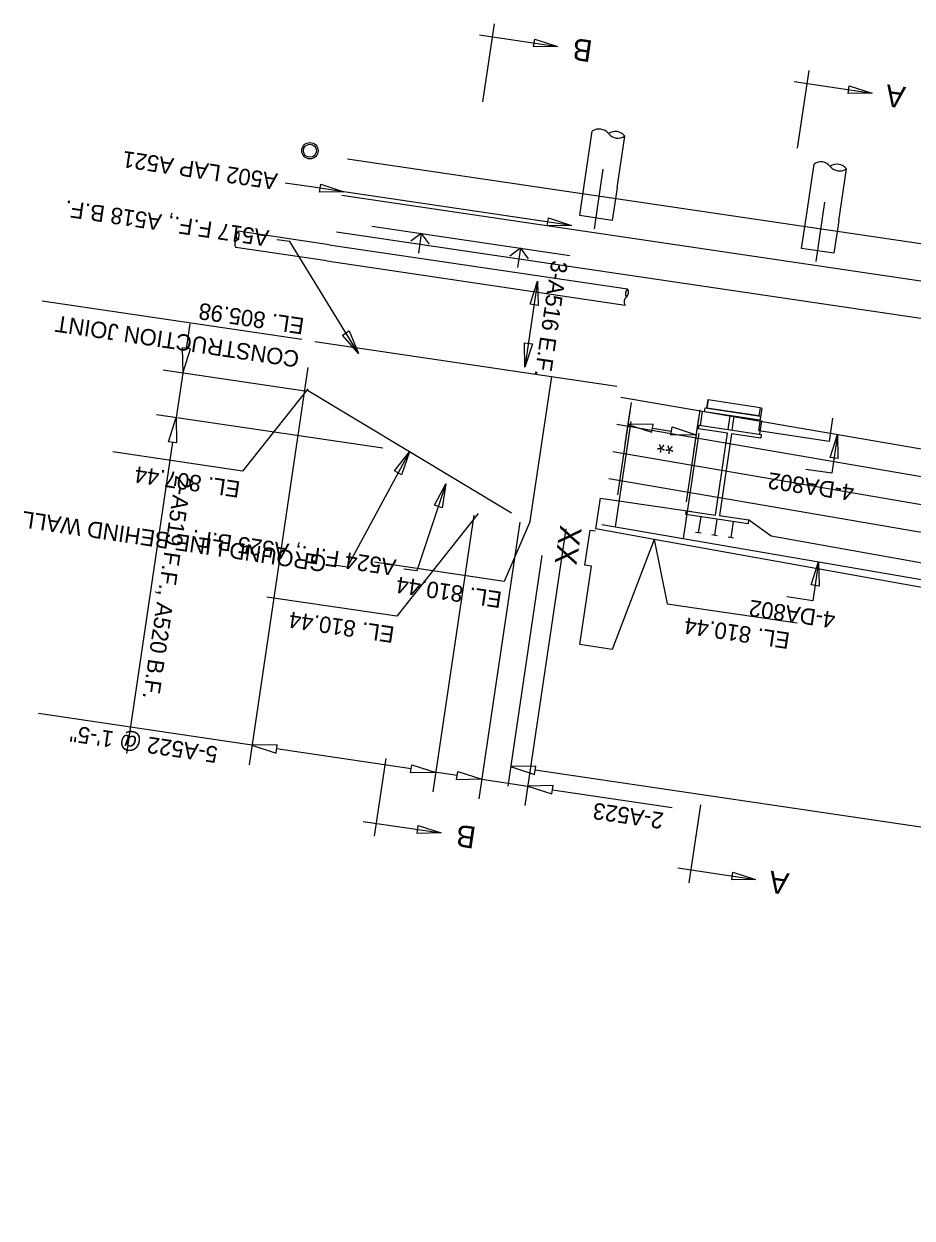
# Model space of a CAD drawing. Extents: x 1468952 to 1469933, y 573916 to 574220.
# Drawn here: x 1468962.44 to 1468989.52, y 574056.5 to 574092.91 of the extents above; entities that cross this region are included whole.
import ezdxf

# ---------------------------------------------------------------- set-up
doc = ezdxf.new("R2010")
doc.units = 0
for name, color, linetype in [('BR_P_Beam_Object', 7, 'Continuous'), ('BR_P_Beam_Stl_Det', 7, 'Continuous'), ('BR_P_Gen_Centerline', 7, 'Continuous'), ('BR_P_Gen_Phase_Construction', 7, 'Continuous'), ('BR_P_Sub_Centerline', 7, 'Continuous'), ('BR_P_Sub_Deep_Centerline', 7, 'Continuous'), ('BR_P_Sub_Foot_Centerline', 7, 'Continuous'), ('BR_P_Sub_Foot_Hidden', 7, 'Continuous'), ('BR_P_Sub_Text', 7, 'Continuous'), ('BR_X_SV_Beam_Seat', 7, 'Continuous'), ('Default', 7, 'Continuous'), ('GE_P_CL_50', 7, 'Continuous'), ('GK_Cells', 7, 'Continuous'), ('PF_X_Ground_Line', 7, 'Continuous'), ('PV_X_EOP', 7, 'Continuous'), ('SV_X_Text_Elevation', 7, 'Continuous'), ('UT_X_Water', 7, 'Continuous')]:
    doc.layers.add(name, color=color, linetype=linetype)

# ---------------------------------------------------------------- blocks, each defined once
blk = doc.blocks.new('arrowOhio')
at = {"layer": 'Default'}
blk.add_lwpolyline([(0.00381, 0.000635), (0.00381, -0.000635), (0, 0)], close=True, dxfattribs=at)

msp = doc.modelspace()

# ---------------------------------------------------------------- linework, layer by layer
at = {"layer": 'BR_P_Beam_Object'}
for p, q in [((1468971.743, 574086.174), (1468980.843, 574084.827)), ((1468971.669, 574085.68), (1468980.77, 574084.333)), ((1468977.303, 574077.995), (1468971.084, 574081.728))]:
    msp.add_line(p, q, dxfattribs=at)
for centre, start, end in [((1468980.955, 574084.684), 127.976, 215.1816), ((1468980.695, 574084.723), 307.976, 35.1816), ((1468980.918, 574084.437), 127.976, 215.1816)]:
    msp.add_arc(centre, 0.181, start, end, dxfattribs=at)
at = {"layer": 'BR_P_Beam_Stl_Det'}
for p, q in [((1468976.432, 574090.535), (1468976.783, 574092.909)), ((1468976.329, 574092.572), (1468978.703, 574092.22)), ((1468986.025, 574089.115), (1468986.377, 574091.489)), ((1468985.922, 574091.152), (1468988.296, 574090.8)), ((1469004.297, 574084.051), (1468972.298, 574088.788)), ((1469010.688, 574081.967), (1468972.133, 574087.675)), ((1469010.523, 574080.854), (1468971.968, 574086.562)), ((1468973.468, 574070.513), (1468973.116, 574068.139)), ((1468983.061, 574069.093), (1468982.709, 574066.719)), ((1468972.779, 574068.593), (1468975.153, 574068.242)), ((1468982.372, 574067.173), (1468984.746, 574066.821))]:
    msp.add_line(p, q, dxfattribs=at)
at = {"layer": 'BR_P_Gen_Centerline'}
for p, q in [((1468971.743, 574086.174), (1468968.973, 574086.585)), ((1468971.669, 574085.68), (1468968.9, 574086.09))]:
    msp.add_line(p, q, dxfattribs=at)
for radius in [0.25, 0.2]:
    msp.add_circle((1468971.156, 574089.041), radius, dxfattribs=at)
for centre, start, end in [((1468969.084, 574086.442), 127.976, 215.1816), ((1468968.825, 574086.48), 307.976, 35.1816), ((1468969.048, 574086.194), 127.976, 215.1816)]:
    msp.add_arc(centre, 0.181, start, end, dxfattribs=at)
at = {"layer": 'BR_P_Gen_Phase_Construction'}
for p, q in [((1468979.531, 574088.054), (1468979.766, 574089.637)), ((1468980.52, 574087.908), (1468980.755, 574089.49)), ((1468986.291, 574087.053), (1468986.525, 574088.636)), ((1468987.28, 574086.907), (1468987.514, 574088.49))]:
    msp.add_line(p, q, dxfattribs=at)
for centre, start, end in [((1468979.974, 574089.341), 37.976, 125.1816), ((1468980.469, 574089.267), 37.976, 125.1816), ((1468980.546, 574089.787), 217.976, 305.1816), ((1468986.734, 574088.34), 37.976, 125.1816), ((1468987.229, 574088.267), 37.976, 125.1816), ((1468987.306, 574088.786), 217.976, 305.1816)]:
    msp.add_arc(centre, 0.362, start, end, dxfattribs=at)
at = {"layer": 'BR_P_Sub_Centerline'}
for p, q in [((1468979.385, 574087.065), (1468979.531, 574088.054)), ((1468980.52, 574087.908), (1468980.374, 574086.918)), ((1468980.374, 574086.918), (1468979.385, 574087.065)), ((1468986.144, 574086.064), (1468986.291, 574087.053)), ((1468987.28, 574086.907), (1468987.134, 574085.918)), ((1468987.134, 574085.918), (1468986.144, 574086.064))]:
    msp.add_line(p, q, dxfattribs=at)
at = {"layer": 'BR_P_Sub_Deep_Centerline'}
msp.add_line((1468977.874, 574077.746), (1468978.527, 574082.158), dxfattribs=at)
at = {"layer": 'BR_P_Sub_Foot_Centerline'}
for p, q in [((1468983.062, 574080.665), (1468983.124, 574081.087)), ((1468983.909, 574080.539), (1468983.972, 574080.962)), ((1468984.028, 574080.522), (1468984.091, 574080.944)), ((1468984.876, 574080.396), (1468984.938, 574080.819))]:
    msp.add_line(p, q, dxfattribs=at)
at = {"layer": 'BR_P_Sub_Foot_Hidden'}
msp.add_line((1468981.648, 574077.187), (1468979.871, 574077.508), dxfattribs=at)
at = {"layer": 'BR_P_Sub_Text'}
for p, q in [((1468980.635, 574081.53), (1468997.15, 574078.687)), ((1468980.947, 574081.36), (1468980.531, 574078.553)), ((1468983.043, 574081.14), (1468982.627, 574078.332)), ((1468980.47, 574077.573), (1468980.946, 574080.788)), ((1468980.512, 574080.703), (1468997.027, 574077.86)), ((1468982.546, 574077.216), (1468983.022, 574080.431)), ((1468980.39, 574079.875), (1468996.905, 574077.032)), ((1468980.267, 574079.048), (1468996.782, 574076.205)), ((1468980.059, 574077.644), (1468996.575, 574074.801))]:
    msp.add_line(p, q, dxfattribs=at)
at = {"layer": 'BR_X_SV_Beam_Seat'}
for p, q in [((1468973.039, 574086.741), (1468979.083, 574085.846)), ((1468974.55, 574086.517), (1468974.229, 574086.279)), ((1468974.55, 574086.517), (1468974.463, 574085.923)), ((1468974.55, 574086.517), (1468974.789, 574086.196)), ((1468977.572, 574086.07), (1468977.251, 574085.831)), ((1468977.572, 574086.07), (1468977.485, 574085.476)), ((1468977.572, 574086.07), (1468977.811, 574085.748)), ((1468970.91, 574083.285), (1468962.997, 574084.457))]:
    msp.add_line(p, q, dxfattribs=at)
msp.add_lwpolyline([(1468987.091, 574080.89), (1468986.986, 574080.179), (1468984.843, 574080.496), (1468984.948, 574081.207)], dxfattribs=at)
at = {"layer": 'GE_P_CL_50'}
for p, q in [((1468983.188, 574081.078), (1468983.206, 574081.202)), ((1468983.206, 574081.202), (1468984.893, 574080.952)), ((1468983.294, 574081.452), (1468983.256, 574081.194)), ((1468984.882, 574081.217), (1468984.843, 574080.959)), ((1468984.875, 574080.828), (1468983.188, 574081.078)), ((1468984.893, 574080.952), (1468984.875, 574080.828))]:
    msp.add_line(p, q, dxfattribs=at)
msp.add_lwpolyline([(1468984.882, 574081.217), (1468984.843, 574080.959), (1468983.256, 574081.194), (1468983.294, 574081.452)], close=True, dxfattribs=at)
at = {"layer": 'GK_Cells'}
for p, q in [((1468983.004, 574080.558), (1468983.021, 574080.671)), ((1468983.892, 574080.426), (1468983.004, 574080.558)), ((1468983.021, 574080.671), (1468984.917, 574080.39)), ((1468983.523, 574077.932), (1468983.892, 574080.426)), ((1468984.012, 574080.408), (1468983.643, 574077.915)), ((1468984.9, 574080.277), (1468984.012, 574080.408)), ((1468984.917, 574080.39), (1468984.9, 574080.277)), ((1468982.618, 574077.951), (1468982.635, 574078.064)), ((1468984.514, 574077.67), (1468982.618, 574077.951)), ((1468982.635, 574078.064), (1468983.523, 574077.932)), ((1468983.071, 574077.884), (1468982.998, 574077.389)), ((1468983.643, 574077.915), (1468984.531, 574077.783)), ((1468983.566, 574077.81), (1468983.493, 574077.316)), ((1468984.061, 574077.737), (1468983.987, 574077.242)), ((1468984.531, 574077.783), (1468984.514, 574077.67)), ((1468983.081, 574077.377), (1468982.916, 574077.401)), ((1468983.575, 574077.303), (1468983.41, 574077.328)), ((1468984.07, 574077.23), (1468983.905, 574077.255))]:
    msp.add_line(p, q, dxfattribs=at)
at = {"layer": 'PF_X_Ground_Line'}
for p, q in [((1468979.871, 574077.508), (1468980.011, 574078.452)), ((1468980.011, 574078.452), (1468982.795, 574078.04)), ((1468979.539, 574076.404), (1468979.698, 574077.476)), ((1468979.698, 574077.476), (1468979.862, 574077.451)), ((1468981.648, 574077.187), (1468980.376, 574073.837)), ((1468981.648, 574077.187), (1468981.648, 574077.187)), ((1468981.648, 574077.187), (1468981.648, 574077.187)), ((1469026.696, 574069.14), (1468981.648, 574077.187)), ((1468979.737, 574076.375), (1468979.539, 574076.404)), ((1468979.383, 574073.984), (1468979.737, 574076.375)), ((1468980.376, 574073.837), (1468979.383, 574073.984))]:
    msp.add_line(p, q, dxfattribs=at)
msp.add_lwpolyline([(1468993.612, 574076.105), (1468992.828, 574075.93), (1468985.216, 574077.29), (1468984.531, 574077.783)], dxfattribs=at)
at = {"layer": 'PV_X_EOP'}
msp.add_line((1468971.306, 574083.227), (1468980.516, 574081.863), dxfattribs=at)
at = {"layer": 'SV_X_Text_Elevation'}
for p, q in [((1468971.195, 574087.94), (1468970.404, 574088.057)), ((1468972.193, 574087.793), (1468971.195, 574087.94)), ((1468972.193, 574087.793), (1468972.193, 574087.793)), ((1468979.13, 574086.766), (1468972.193, 574087.793)), ((1468970.539, 574086.269), (1468970.143, 574086.328)), ((1468972.634, 574082.862), (1468970.539, 574086.269)), ((1468978.099, 574085.065), (1468977.711, 574082.447)), ((1468967.389, 574083.016), (1468967.501, 574083.768)), ((1468970.997, 574081.713), (1468966.684, 574082.352)), ((1468967.278, 574082.264), (1468967.076, 574080.903)), ((1468971.094, 574082.427), (1468969.301, 574070.321)), ((1468971.092, 574081.782), (1468969.104, 574079.275)), ((1468980.911, 574081.123), (1468980.76, 574080.099)), ((1468973.38, 574079.97), (1468966.483, 574080.991)), ((1468983.008, 574080.902), (1468982.843, 574079.79)), ((1468981.599, 574080.581), (1468982.179, 574080.495)), ((1468987.241, 574080.393), (1468987.065, 574079.206)), ((1468966.965, 574080.151), (1468965.56, 574070.66)), ((1468969.104, 574079.275), (1468965.147, 574079.861)), ((1468974.193, 574079.862), (1468972.29, 574076.344)), ((1468987.065, 574079.206), (1468986.274, 574079.323)), ((1468975.301, 574078.886), (1468974.417, 574076.229)), ((1468976.289, 574077.98), (1468973.804, 574074.846)), ((1468976.156, 574077.926), (1468974.907, 574069.491)), ((1468977.557, 574077.718), (1468976.308, 574069.284)), ((1468977.874, 574077.746), (1468977.079, 574075.91)), ((1468978.958, 574077.511), (1468977.71, 574069.076)), ((1468981.648, 574077.187), (1468982.05, 574075.228)), ((1468972.29, 574076.344), (1468971.894, 574076.402)), ((1468977.079, 574075.91), (1468973.122, 574076.496)), ((1468978.226, 574076.7), (1468977.186, 574069.669)), ((1468986.665, 574076.507), (1468986.49, 574075.32)), ((1468974.417, 574076.229), (1468974.021, 574076.288)), ((1468973.804, 574074.846), (1468969.847, 574075.432)), ((1468986.49, 574075.32), (1468985.698, 574075.437)), ((1468982.05, 574075.228), (1468986.007, 574074.642)), ((1468969.389, 574070.915), (1468962.882, 574071.878)), ((1468974.243, 574070.196), (1468970.141, 574070.803)), ((1468975.644, 574069.989), (1468974.893, 574070.1)), ((1468976.396, 574069.877), (1468977.798, 574069.67)), ((1469070.259, 574056.497), (1468978.025, 574070.152)), ((1468978.549, 574069.559), (1468982.202, 574069.018))]:
    msp.add_line(p, q, dxfattribs=at)
for points in [[(1468967.515, 574082.997), (1468967.264, 574083.034), (1468967.278, 574082.264)], [(1468967.09, 574080.133), (1468966.84, 574080.17), (1468967.076, 574080.903)], [(1468981.581, 574080.456), (1468981.618, 574080.706), (1468980.848, 574080.692)], [(1468982.161, 574080.37), (1468982.198, 574080.621), (1468982.931, 574080.384)], [(1468970.123, 574070.678), (1468970.16, 574070.929), (1468969.389, 574070.915)], [(1468974.224, 574070.071), (1468974.262, 574070.321), (1468974.995, 574070.085)], [(1468978.007, 574070.026), (1468978.044, 574070.277), (1468977.273, 574070.263)], [(1468975.626, 574069.863), (1468975.663, 574070.114), (1468976.396, 574069.877)], [(1468978.531, 574069.433), (1468978.568, 574069.684), (1468977.798, 574069.67)]]:
    msp.add_lwpolyline(points, close=True, dxfattribs=at)
at = {"layer": 'UT_X_Water'}
for p, q in [((1468979.831, 574086.662), (1468980.099, 574088.475)), ((1468986.59, 574085.661), (1468986.859, 574087.475))]:
    msp.add_line(p, q, dxfattribs=at)

# ---------------------------------------------------------------- block references
at = {"layer": 'BR_P_Beam_Stl_Det', "xscale": 188.97600000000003, "yscale": 188.97599999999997, "rotation": 171.57876932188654}
for p in [(1468978.703, 574092.22), (1468988.296, 574090.8), (1468975.153, 574068.242), (1468984.746, 574066.821)]:
    msp.add_blockref('arrowOhio', p, dxfattribs=at)
at = {"layer": 'SV_X_Text_Elevation'}
for p, xscale, yscale, rotation in [((1468972.193, 574087.793), 191.49568000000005, 191.49568, 171.57876932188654), ((1468979.13, 574086.766), 191.49568000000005, 191.49568, 171.57876932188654), ((1468978.099, 574085.065), 191.49568000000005, 191.49568, -98.42123067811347), ((1468972.634, 574082.862), 191.49568, 191.49568, 121.57876932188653), ((1468977.711, 574082.447), 191.49568000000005, 191.49568, 81.57876932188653), ((1468987.241, 574080.393), 191.49568000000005, 191.49568, -98.42123067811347), ((1468974.193, 574079.862), 191.49568000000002, 191.49567999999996, -118.42123067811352), ((1468975.301, 574078.886), 191.49568000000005, 191.49568000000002, -108.42123067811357), ((1468986.665, 574076.507), 191.49568000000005, 191.49568, -98.42123067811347)]:
    msp.add_blockref('arrowOhio', p, dxfattribs=dict(at, xscale=xscale, yscale=yscale, rotation=rotation))

# ---------------------------------------------------------------- texts
for s, height, rotation, p in [('B', 0.665, 171.5788, (1468979.802, 574092.394)), ('A', 0.665, 171.5788, (1468989.341, 574090.981)), ('A502 LAP A521', 0.5, 171.5788, (1468970.193, 574088.341)), ('A517 F.F., A518 B.F.', 0.5, 171.5788, (1468969.933, 574086.612)), ('3-A516 E.F.', 0.5, 261.5788, (1468978.524, 574085.715)), ('EL. 805.98', 0.5, 171.5788, (1468971.006, 574083.932)), ('CONSTRUCTION JOINT', 0.5, 171.5788, (1468970.857, 574082.923)), ('**', 0.5, 171.5788, (1468982.301, 574080.275)), ('EL. 807.44', 0.5, 171.5788, (1468969.056, 574078.953)), ('2-A519 F.F., A520 B.F.', 0.5, 261.5788, (1468967.062, 574079.157)), ('4-DA802', 0.5, 171.5788, (1468987.774, 574078.853)), ('GROUND LINE BEHIND WALL', 0.5, 171.5788, (1468971.683, 574076.686)), ('A524 F.F., A525 B.F.', 0.5, 171.5788, (1468973.81, 574076.572)), ('XX', 0.665, 261.5788, (1468978.792, 574077.644)), ('EL. 810.44', 0.5, 171.5788, (1468977.031, 574075.588)), ('4-DA802', 0.5, 171.5788, (1468987.199, 574074.966)), ('EL. 810.44', 0.5, 171.5788, (1468973.756, 574074.524)), ('EL. 810.44', 0.5, 171.5788, (1468985.813, 574074.341)), ('5-A522 @ 1\'-5"', 0.5, 171.5788, (1468968.371, 574070.863)), ('2-A523', 0.5, 171.5788, (1468981.963, 574068.851)), ('B', 0.665, 171.5788, (1468976.252, 574068.415)), ('A', 0.665, 171.5788, (1468985.791, 574067.003))]:
    msp.add_text(s, height=height, rotation=rotation, dxfattribs=at).set_placement(p)

doc.saveas('drawing.dxf')
